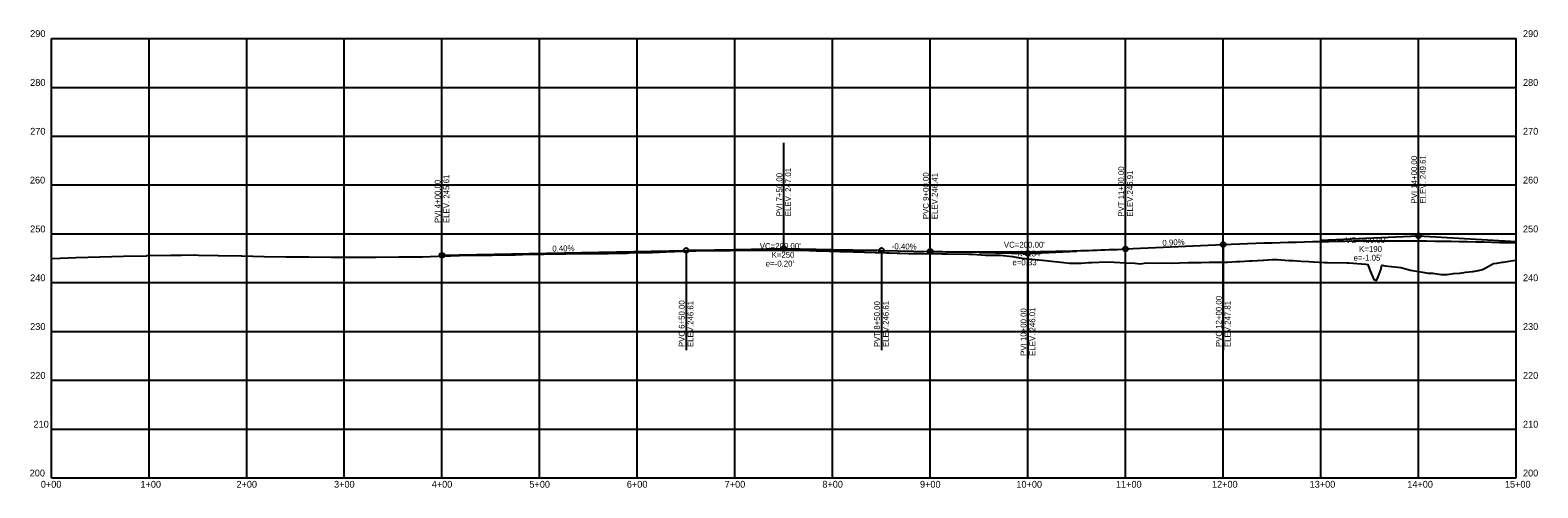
# Model space of a CAD drawing. Extents: x 1939726 to 1943270, y 529766 to 530234.
# Drawn here: x 1939726 to 1941270, y 529766 to 530234 of the extents above; entities that cross this region are included whole.
import ezdxf

# ---------------------------------------------------------------- set-up
doc = ezdxf.new("R2010")
doc.units = 0
for name, color, linetype in [('R_Axis', 7, 'Continuous'), ('R_Axis Annot', 7, 'Continuous'), ('R_Exist Surface', 7, 'Continuous'), ('R_Grid', 7, 'Continuous'), ('R_Vert Alg', 7, 'Continuous'), ('R_Vert Alg Annot', 7, 'Continuous')]:
    doc.layers.add(name, color=color, linetype=linetype)

msp = doc.modelspace()

# ---------------------------------------------------------------- linework, layer by layer
at = {"layer": 'R_Axis'}
for p, q in [((1939747.8, 529775.8), (1939747.8, 530225.8)), ((1941247.8, 529775.8), (1941247.8, 530225.8)), ((1939747.8, 529775.8), (1941247.8, 529775.8))]:
    msp.add_line(p, q, dxfattribs=at)
at = {"layer": 'R_Exist Surface'}
msp.add_lwpolyline([(1939747.8, 529999.1), (1939748.5, 530000.5), (1939748.8, 530000.5), (1939773, 530001.4), (1939773.3, 530001.4), (1939797.5, 530002.3), (1939797.8, 530002.3), (1939821.5, 530002.9), (1939821.7, 530002.9), (1939845.5, 530003.4), (1939845.6, 530003.5), (1939870.1, 530003.8), (1939870.2, 530003.8), (1939881.1, 530004), (1939894.8, 530004.2), (1939894.8, 530004.2), (1939898.4, 530004.1), (1939918.6, 530003.7), (1939918.8, 530003.7), (1939942.5, 530003.2), (1939942.9, 530003.2), (1939965.4, 530002.7), (1939965.6, 530002.7), (1939988.2, 530002.3), (1940011.2, 530002.1), (1940011.3, 530002.1), (1940011.4, 530002.1), (1940034.4, 530002), (1940034.5, 530002), (1940057.4, 530001.9), (1940079.9, 530001.9), (1940080.5, 530001.9), (1940103.6, 530002.1), (1940104.1, 530002.1), (1940127.3, 530002.3), (1940127.7, 530002.3), (1940151.5, 530003.1), (1940151.6, 530003.1), (1940156.9, 530003.3), (1940175.1, 530003.8), (1940175.4, 530003.8), (1940187.3, 530004), (1940198.7, 530004.1), (1940199, 530004.1), (1940199.3, 530004.1), (1940222.6, 530004.3), (1940229.9, 530004.5), (1940230.1, 530004.5), (1940251.9, 530004.9), (1940252.2, 530004.9), (1940274.1, 530005.4), (1940274.3, 530005.4), (1940274.6, 530005.4), (1940296.2, 530005.5), (1940315.9, 530005.6), (1940318.2, 530005.6), (1940337.4, 530006.1), (1940339.8, 530006.2), (1940358.9, 530006.7), (1940361.5, 530006.8), (1940363.2, 530006.8), (1940384.6, 530007.7), (1940386.4, 530007.7), (1940407.6, 530008.5), (1940409.5, 530008.6), (1940411.4, 530008.6), (1940422.6, 530008.7), (1940443.3, 530008.8), (1940445.2, 530008.9), (1940445.7, 530008.9), (1940456.4, 530008.9), (1940466.7, 530009), (1940467.7, 530009), (1940468.7, 530009), (1940470.7, 530009), (1940479, 530009), (1940490.3, 530009), (1940493.7, 530008.9), (1940494.9, 530008.9), (1940501.5, 530008.9), (1940512.8, 530008.9), (1940518.7, 530008.9), (1940518.7, 530008.9), (1940519.2, 530008.9), (1940524.1, 530008.7), (1940531, 530008.5), (1940532.2, 530008.5), (1940535.3, 530008.4), (1940544.4, 530008.1), (1940546.6, 530008.1), (1940555.2, 530007.8), (1940557.9, 530007.7), (1940559.2, 530007.7), (1940569.1, 530007.4), (1940569.7, 530007.4), (1940575.8, 530007.2), (1940580.4, 530007), (1940591.7, 530006.7), (1940593.1, 530006.7), (1940602.9, 530006.3), (1940606.1, 530006.2), (1940614.2, 530006), (1940616.7, 530005.9), (1940625.5, 530005.8), (1940627.8, 530005.8), (1940636.7, 530005.7), (1940640.9, 530005.6), (1940659.6, 530005.3), (1940664.8, 530005.3), (1940687.3, 530005), (1940687.9, 530004.9), (1940688.3, 530004.9), (1940691.2, 530004.9), (1940704.3, 530004), (1940716.3, 530003.9), (1940719.3, 530003.8), (1940732.1, 530002.4), (1940741.3, 530001), (1940748.4, 530000.2), (1940765.9, 529998.6), (1940784.6, 529996.5), (1940790.3, 529995.9), (1940802.2, 529995.9), (1940809.9, 529996.5), (1940813.3, 529996.4), (1940827.8, 529997), (1940836.3, 529996.8), (1940848.2, 529996.2), (1940857.3, 529995.8), (1940862.8, 529995.2), (1940868.9, 529996), (1940880.3, 529995.8), (1940885.9, 529996), (1940895.9, 529995.9), (1940903, 529996.1), (1940912.2, 529996.5), (1940925.3, 529996.5), (1940933.3, 529996.7), (1940947.5, 529996.7), (1940952.2, 529996.8), (1940961.2, 529997.3), (1940964.7, 529997.4), (1940974.9, 529998), (1940977.1, 529998), (1940988.6, 529998.8), (1940989.5, 529998.8), (1940998.2, 529999.4), (1941002.3, 529999.5), (1941003, 529999.5), (1941014.9, 529998.6), (1941019.4, 529998.4), (1941027.6, 529997.8), (1941035.5, 529997.4), (1941040.4, 529997), (1941051.5, 529996.5), (1941053.2, 529996.4), (1941054.5, 529996.3), (1941074.4, 529996.2), (1941074.5, 529996.2), (1941076.4, 529996.2), (1941093.8, 529994.8), (1941096, 529994.5), (1941098, 529988.7), (1941102.2, 529979), (1941104.7, 529978.1), (1941106.4, 529981.7), (1941109.2, 529988.8), (1941110.3, 529993.6), (1941113.6, 529993), (1941129.6, 529991.2), (1941139.5, 529988.5), (1941149.9, 529987), (1941151.9, 529986.6), (1941157.8, 529985.5), (1941158.3, 529985.5), (1941162.6, 529985.4), (1941164.6, 529985), (1941171, 529984.1), (1941171, 529984.1), (1941175.6, 529984.1), (1941177.3, 529984.3), (1941183.6, 529985.2), (1941183.6, 529985.2), (1941189.4, 529985.5), (1941190, 529985.6), (1941196.3, 529986.6), (1941196.4, 529986.6), (1941202.7, 529987.2), (1941203.8, 529987.3), (1941209, 529988.3), (1941209.3, 529988.3), (1941213.4, 529989.2), (1941215.4, 529990.2), (1941221.7, 529993.7), (1941224.7, 529995.4), (1941228, 529995.9), (1941231.7, 529996.5), (1941233.6, 529996.7), (1941234.4, 529996.8), (1941240.7, 529997.8), (1941247.1, 529998.8), (1941247.8, 529998.9)], dxfattribs=at)
at = {"layer": 'R_Grid'}
for p, q in [((1939747.8, 530225.8), (1941247.8, 530225.8)), ((1939747.8, 530225.8), (1941247.8, 530225.8)), ((1939847.8, 529775.8), (1939847.8, 530225.8)), ((1939947.8, 529775.8), (1939947.8, 530225.8)), ((1940047.8, 529775.8), (1940047.8, 530225.8)), ((1940147.8, 529775.8), (1940147.8, 530225.8)), ((1940247.8, 529775.8), (1940247.8, 530225.8)), ((1940347.8, 529775.8), (1940347.8, 530225.8)), ((1940447.8, 529775.8), (1940447.8, 530225.8)), ((1940547.8, 529775.8), (1940547.8, 530225.8)), ((1940647.8, 529775.8), (1940647.8, 530225.8)), ((1940747.8, 529775.8), (1940747.8, 530225.8)), ((1940847.8, 529775.8), (1940847.8, 530225.8)), ((1940947.8, 529775.8), (1940947.8, 530225.8)), ((1941047.8, 529775.8), (1941047.8, 530225.8)), ((1941147.8, 529775.8), (1941147.8, 530225.8)), ((1939747.8, 530175.8), (1941247.8, 530175.8)), ((1939747.8, 530125.8), (1941247.8, 530125.8)), ((1939747.8, 530075.8), (1941247.8, 530075.8)), ((1939747.8, 530025.8), (1941247.8, 530025.8)), ((1939747.8, 529975.8), (1941247.8, 529975.8)), ((1939747.8, 529925.8), (1941247.8, 529925.8)), ((1939747.8, 529875.8), (1941247.8, 529875.8)), ((1939747.8, 529825.8), (1941247.8, 529825.8))]:
    msp.add_line(p, q, dxfattribs=at)
at = {"layer": 'R_Vert Alg'}
for p, q in [((1941047.8, 530019.3), (1941147.8, 530023.8)), ((1941147.8, 530023.8), (1941247.8, 530017.8)), ((1940147.8, 530003.8), (1940397.8, 530008.8)), ((1940447.8, 530009.8), (1940497.8, 530010.8)), ((1940497.8, 530010.8), (1940547.8, 530009.8)), ((1940597.8, 530008.8), (1940647.8, 530007.8)), ((1940697.8, 530006.8), (1940747.8, 530005.8)), ((1940747.8, 530005.8), (1940797.8, 530008.1)), ((1940847.8, 530010.3), (1940947.8, 530014.8))]:
    msp.add_line(p, q, dxfattribs=at)
for points in [[(1940397.8, 530008.8), (1940401.9, 530008.9), (1940406.1, 530009), (1940410.3, 530009), (1940414.4, 530009.1), (1940418.6, 530009.2), (1940422.8, 530009.2), (1940426.9, 530009.3), (1940431.1, 530009.4), (1940435.3, 530009.4), (1940439.4, 530009.5), (1940443.6, 530009.5), (1940447.8, 530009.6), (1940451.9, 530009.6), (1940456.1, 530009.6), (1940460.3, 530009.7), (1940464.4, 530009.7), (1940468.6, 530009.7), (1940472.8, 530009.7), (1940476.9, 530009.8), (1940481.1, 530009.8), (1940485.3, 530009.8), (1940489.4, 530009.8), (1940493.6, 530009.8), (1940501.9, 530009.8), (1940506.1, 530009.8), (1940510.3, 530009.8), (1940514.4, 530009.8), (1940518.6, 530009.8), (1940522.8, 530009.7), (1940526.9, 530009.7), (1940531.1, 530009.7), (1940535.3, 530009.7), (1940539.4, 530009.6), (1940543.6, 530009.6), (1940547.8, 530009.6), (1940551.9, 530009.5), (1940556.1, 530009.5), (1940560.3, 530009.4), (1940564.4, 530009.4), (1940568.6, 530009.3), (1940572.8, 530009.2), (1940576.9, 530009.2), (1940581.1, 530009.1), (1940585.3, 530009), (1940589.4, 530009), (1940593.6, 530008.9), (1940597.8, 530008.8)], [(1940647.8, 530007.8), (1940651.9, 530007.7), (1940656.1, 530007.7), (1940660.3, 530007.6), (1940664.4, 530007.5), (1940668.6, 530007.5), (1940672.8, 530007.4), (1940676.9, 530007.4), (1940681.1, 530007.3), (1940685.3, 530007.3), (1940689.4, 530007.3), (1940693.6, 530007.2), (1940697.8, 530007.2), (1940701.9, 530007.2), (1940706.1, 530007.2), (1940710.3, 530007.2), (1940714.4, 530007.2), (1940718.6, 530007.2), (1940722.8, 530007.2), (1940726.9, 530007.2), (1940731.1, 530007.3), (1940735.3, 530007.3), (1940739.4, 530007.3), (1940743.6, 530007.4), (1940751.9, 530007.5), (1940756.1, 530007.5), (1940760.3, 530007.6), (1940764.4, 530007.7), (1940768.6, 530007.8), (1940772.8, 530007.8), (1940776.9, 530007.9), (1940781.1, 530008), (1940785.3, 530008.1), (1940789.4, 530008.2), (1940793.6, 530008.3), (1940797.8, 530008.5), (1940801.9, 530008.6), (1940806.1, 530008.7), (1940810.3, 530008.8), (1940814.4, 530009), (1940818.6, 530009.1), (1940822.8, 530009.3), (1940826.9, 530009.4), (1940831.1, 530009.6), (1940835.3, 530009.8), (1940839.4, 530009.9), (1940843.6, 530010.1), (1940847.8, 530010.3)], [(1940947.8, 530014.8), (1940956.1, 530015.2), (1940964.4, 530015.5), (1940972.8, 530015.8), (1940981.1, 530016.2), (1940989.4, 530016.5), (1940997.8, 530016.7), (1941006.1, 530017), (1941014.4, 530017.2), (1941022.8, 530017.4), (1941031.1, 530017.6), (1941039.4, 530017.8), (1941047.8, 530018), (1941056.1, 530018.1), (1941064.4, 530018.3), (1941072.8, 530018.4), (1941081.1, 530018.5), (1941089.4, 530018.5), (1941097.8, 530018.6), (1941106.1, 530018.6), (1941114.4, 530018.7), (1941122.8, 530018.7), (1941131.1, 530018.6), (1941139.4, 530018.6), (1941156.1, 530018.5), (1941164.4, 530018.4), (1941172.8, 530018.3), (1941181.1, 530018.2), (1941189.4, 530018), (1941197.8, 530017.9), (1941206.1, 530017.7), (1941214.4, 530017.5), (1941222.8, 530017.3), (1941231.1, 530017), (1941239.4, 530016.8), (1941247.8, 530016.5)]]:
    msp.add_lwpolyline(points, dxfattribs=at)
at = {"layer": 'R_Vert Alg Annot'}
for p, q in [((1941147.8, 530053.8), (1941147.8, 530131.8)), ((1940497.8, 530040.8), (1940497.8, 530118.8)), ((1940847.8, 530040.3), (1940847.8, 530118.3)), ((1940147.8, 530033.8), (1940147.8, 530111.8)), ((1940647.8, 530037.8), (1940647.8, 530109.8)), ((1941147.8, 530023.8), (1941147.8, 530053.8)), ((1940497.8, 530010.8), (1940497.8, 530040.8)), ((1940647.8, 530007.8), (1940647.8, 530037.8)), ((1940847.8, 530010.3), (1940847.8, 530040.3)), ((1940147.8, 530003.8), (1940147.8, 530033.8)), ((1940397.8, 530008.8), (1940397.8, 529978.8)), ((1940597.8, 530008.8), (1940597.8, 529978.8)), ((1940947.8, 530014.8), (1940947.8, 529984.8)), ((1940747.8, 530005.8), (1940747.8, 529975.8)), ((1940397.8, 529978.8), (1940397.8, 529906.8)), ((1940597.8, 529978.8), (1940597.8, 529906.8)), ((1940747.8, 529975.8), (1940747.8, 529897.8)), ((1940947.8, 529984.8), (1940947.8, 529906.8))]:
    msp.add_line(p, q, dxfattribs=at)
for centre in [(1941147.8, 530023.8), (1940147.8, 530003.8), (1940397.8, 530008.8), (1940497.8, 530010.8), (1940597.8, 530008.8), (1940647.8, 530007.8), (1940747.8, 530005.8), (1940847.8, 530010.3), (1940947.8, 530014.8)]:
    msp.add_circle(centre, 2.5, dxfattribs=at)

# ---------------------------------------------------------------- texts
at = {"layer": 'R_Axis Annot'}
for s, height, p in [('290', 7, (1939726.1, 530227.3)), ('290', 7, (1939726.1, 530227.3)), ('290', 7, (1941254.8, 530227.3)), ('290', 7, (1941254.8, 530227.3)), ('280', 7, (1939726.1, 530177.3)), ('280', 7, (1941254.8, 530177.3)), ('270', 7, (1939726.1, 530127.3)), ('270', 7, (1941254.8, 530127.3)), ('260', 7, (1939725.8, 530077.3)), ('260', 7, (1941254.8, 530077.3)), ('250', 7, (1939726.1, 530027.3)), ('250', 7, (1941254.8, 530027.3)), ('240', 7, (1939726.1, 529977.3)), ('240', 7, (1941254.8, 529977.3)), ('230', 7, (1939726.1, 529927.3)), ('230', 7, (1941254.8, 529927.3)), ('220', 7, (1939726.1, 529877.3)), ('220', 7, (1941254.8, 529877.3)), ('210', 7, (1939729.5, 529827.3)), ('210', 7, (1941254.8, 529827.3)), ('200', 7, (1939725.6, 529777.3)), ('-', 0.0001, (1939747.8, 529775.8)), ('200', 7, (1941254.8, 529777.3)), ('0+00', 7, (1939737, 529765.8)), ('1+00', 7, (1939839, 529765.8)), ('2+00', 7, (1939937.3, 529765.8)), ('3+00', 7, (1940037.3, 529765.8)), ('4+00', 7, (1940137.3, 529765.8)), ('5+00', 7, (1940237.3, 529765.8)), ('6+00', 7, (1940337.1, 529765.8)), ('7+00', 7, (1940437.3, 529765.8)), ('8+00', 7, (1940537.3, 529765.8)), ('9+00', 7, (1940637.3, 529765.8)), ('10+00', 7, (1940736, 529765.8)), ('11+00', 7, (1940838, 529765.8)), ('12+00', 7, (1940936.3, 529765.8)), ('13+00', 7, (1941036.3, 529765.8)), ('14+00', 7, (1941136.3, 529765.8)), ('15+00', 7, (1941236.3, 529765.8))]:
    msp.add_text(s, height=height, dxfattribs=at).set_placement(p)
at = {"layer": 'R_Vert Alg Annot'}
for s, rotation, p in [('PVI 14+00.00', 90, (1941146.3, 530056.8)), ('ELEV. 249.61', 90, (1941155.3, 530056.8)), ('ELEV. 245.61', 90, (1940155.3, 530036.8)), ('PVI 7+50.00', 90, (1940496.3, 530043.8)), ('ELEV. 247.01', 90, (1940505.3, 530043.8)), ('PVC 9+00.00', 90, (1940646.3, 530040.8)), ('ELEV.246.41', 90, (1940655.3, 530040.8)), ('PVT 11+00.00', 90, (1940846.3, 530043.3)), ('ELEV.246.91', 90, (1940855.3, 530043.3)), ('PVI 4+00.00', 90, (1940146.3, 530036.8)), ('0.40%', 1.1458, (1940260.8, 530007.6)), ('-0.40%', 358.8542, (1940608.4, 530010.1)), ('0.90%', 2.5766, (1940885.7, 530013.5)), ('PVC 12+00.00', 90, (1940946.3, 529909.8)), ('PVC 6+50.00', 90, (1940396.3, 529909.8)), ('ELEV.246.61', 90, (1940405.3, 529909.8)), ('PVT 8+50.00', 90, (1940596.3, 529909.8)), ('ELEV.246.61', 90, (1940605.3, 529909.8)), ('PVI 10+00.00', 90, (1940746.3, 529900.8)), ('ELEV. 246.01', 90, (1940755.3, 529900.8)), ('ELEV.247.81', 90, (1940955.3, 529909.8))]:
    msp.add_text(s, height=6, rotation=rotation, dxfattribs=at).set_placement(p)
for s, p in [("VC=400.00'", (1941073.2, 530016.3)), ("VC=200.00'", (1940473.2, 530010.3)), ('K=250', (1940485.3, 530001.3)), ("VC=200.00'", (1940723.2, 530011.6)), ('K=154', (1940737.2, 530002.6)), ('K=190', (1941087, 530007.3)), ("e=-0.20'", (1940479.3, 529992.3)), ("e=0.33'", (1940732, 529993.6)), ("e=-1.05'", (1941081.3, 529998.3))]:
    msp.add_text(s, height=6, dxfattribs=at).set_placement(p)

doc.saveas('drawing.dxf')
